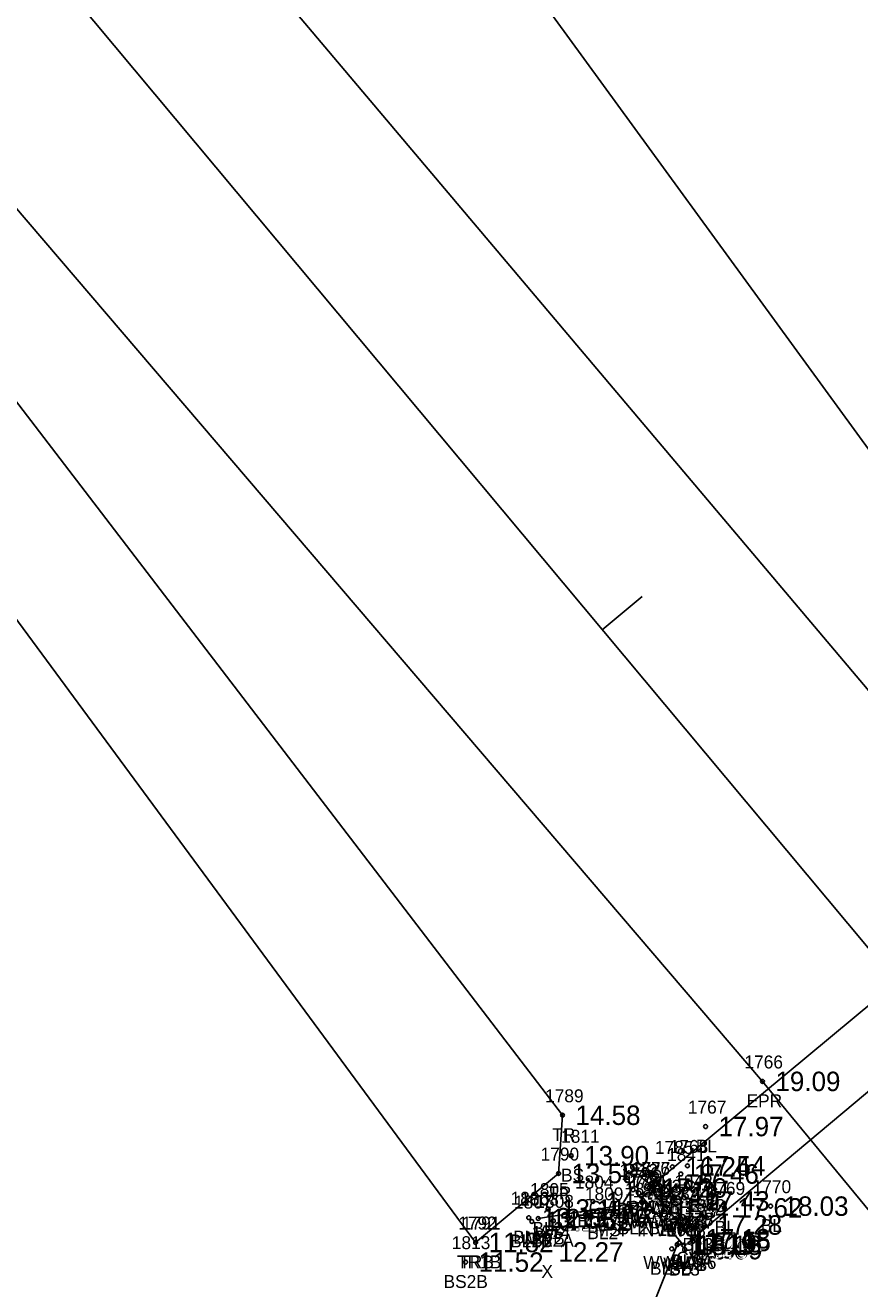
# Model space of a CAD drawing. Extents: x 2042117 to 2045853, y 303080 to 309569.
# Drawn here: x 2043937.2 to 2044001.6, y 305237.3 to 305334.8 of the extents above; entities that cross this region are included whole.
import ezdxf

# ---------------------------------------------------------------- set-up
doc = ezdxf.new("R2010")
doc.units = 0
for name, color, linetype in [('RD_DTM_BkLn_txCode', 7, 'Continuous'), ('RD_EX_Bridge', 7, 'Continuous'), ('RD_EX_Bridge_txCode', 7, 'Continuous'), ('RD_EX_Misc_txCode', 7, 'Continuous'), ('RD_EX_Road', 7, 'Continuous'), ('RD_EX_Road_txCode', 7, 'Continuous'), ('RD_EX_TX_Bridge_ELEV', 7, 'Continuous'), ('RD_EX_TX_Misc_ELEV', 7, 'Continuous'), ('RD_EX_TX_Road_ELEV', 7, 'Continuous'), ('RD_EX_TX_VEG_ELEV', 7, 'Continuous'), ('RD_EX_VEG', 7, 'Continuous'), ('RD_EX_VEG_txCode', 7, 'Continuous'), ('RD_HC_Cl', 7, 'Continuous'), ('RD_HC_Data_Tic', 7, 'Continuous'), ('RD_SMD_Locator', 7, 'Continuous')]:
    doc.layers.add(name, color=color, linetype=linetype)

msp = doc.modelspace()

# ---------------------------------------------------------------- linework, layer by layer
at = {"layer": 'RD_EX_Bridge'}
msp.add_line((2043984.777, 305244.422), (2043988.039, 305240.628), dxfattribs=at)
for points in [[(2043985.386, 305245.047), (2043988.72, 305241.13), (2044027.046, 305273.236), (2044023.87, 305277.035), (2043985.386, 305245.047)], [(2043984.895, 305244.066), (2043984.8, 305243.944), (2043976.82, 305242.688)], [(2043987.689, 305240.793), (2043987.547, 305240.669), (2043984.387, 305232.741)]]:
    msp.add_lwpolyline(points, dxfattribs=at)
at = {"layer": 'RD_EX_Road'}
for points in [[(2043522.114, 305819.999), (2043547.67, 305789.846), (2043610.716, 305713.317), (2043674.952, 305636.321), (2043738.181, 305559.625), (2043802.423, 305482.711), (2043865.72, 305405.842), (2043929.527, 305328.852), (2043994.128, 305253.275), (2044057.402, 305176.499), (2044121.268, 305100.203), (2044185.29, 305023.535), (2044249.556, 304947.279), (2044313.307, 304870.314), (2044377.087, 304793.291), (2044441.996, 304716.26), (2044505.918, 304639.554), (2044570.444, 304562.352), (2044634.611, 304485.931), (2044698.462, 304409.271), (2044762.461, 304332.365)], [(2043821.87, 305499.098), (2043885.809, 305423.073), (2043949.559, 305345.929), (2044013.411, 305270.34), (2044077.969, 305194.148), (2044141.399, 305117.67), (2044205.924, 305040.831), (2044269.544, 304964.65), (2044331.732, 304891.037), (2044335.217, 304889.195), (2044346.013, 304875.314), (2044356.182, 304867.608), (2044370.01, 304868.141), (2044386.833, 304866.361), (2044389.438, 304849.531), (2044390.713, 304830.729), (2044393.769, 304818.438), (2044395.505, 304814.177), (2044398.156, 304811.088)]]:
    msp.add_lwpolyline(points, dxfattribs=at)
at = {"layer": 'RD_EX_VEG'}
for points in [[(2043547.512, 305881.496), (2043539.704, 305861.319), (2043541.738, 305855.072), (2043567.734, 305828.704), (2043642.401, 305738.289), (2043706.881, 305661.84), (2043768.334, 305586.863), (2043834.286, 305506.383), (2043895.633, 305432.164), (2043964.517, 305353.987), (2044012.412, 305288.228), (2044020.961, 305286.081), (2044026.635, 305287.127), (2044039.882, 305282.355)], [(2043510.516, 305810.422), (2043502.87, 305810.614), (2043504.866, 305802.248), (2043509.115, 305791.368), (2043594.274, 305695.691), (2043658.161, 305620.889), (2043717.857, 305542.894), (2043784.348, 305466.308), (2043848.974, 305392.369), (2043916.007, 305316.786), (2043971.984, 305240.839)], [(2043510.516, 305810.422), (2043528.576, 305788.549), (2043603.52, 305706.798), (2043669.107, 305631.483), (2043746.08, 305529.273), (2043781.83, 305496.014), (2043793.112, 305482.335), (2043857.161, 305399.039), (2043922.607, 305323.928), (2043978.692, 305250.662), (2043978.387, 305246.162), (2043971.984, 305240.839)]]:
    msp.add_lwpolyline(points, dxfattribs=at)
at = {"layer": 'RD_HC_Cl'}
msp.add_line((2043284.298, 306123.239), (2045221.309, 303803.998), dxfattribs=at)
at = {"layer": 'RD_HC_Data_Tic'}
msp.add_line((2043981.766, 305288.14), (2043984.836, 305290.704), dxfattribs=at)
at = {"layer": 'RD_SMD_Locator'}
for centre in [(2043994.128, 305253.275), (2043978.692, 305250.662), (2043989.737, 305249.789), (2043979.36, 305247.538), (2043987.173, 305246.68), (2043988.335, 305246.753), (2043978.387, 305246.162), (2043987.826, 305246.125), (2043984.139, 305244.907), (2043984.596, 305244.651), (2043984.777, 305244.422), (2043985.386, 305245.047), (2043985.386, 305245.047), (2043977.578, 305243.425), (2043981.036, 305244.002), (2043984.624, 305243.458), (2043984.8, 305243.944), (2043984.895, 305244.066), (2043988.659, 305244.049), (2043991.187, 305243.513), (2043994.754, 305243.646), (2043976.087, 305242.751), (2043976.326, 305242.457), (2043976.82, 305242.688), (2043977.982, 305242.512), (2043981.806, 305243.093), (2043989.627, 305242.189), (2043971.984, 305240.839), (2043971.984, 305240.839), (2043987.547, 305240.669), (2043987.689, 305240.793), (2043988.039, 305240.628), (2043988.72, 305241.13), (2043988.758, 305240.917), (2043987.122, 305240.347), (2043988.119, 305240.286), (2043971.209, 305239.325)]:
    msp.add_circle(centre, 0.15, dxfattribs=at)

# ---------------------------------------------------------------- texts
at = {"layer": 'RD_DTM_BkLn_txCode'}
for s, p in [('1767', (2043988.367, 305250.789)), ('1811', (2043978.58, 305248.538)), ('1785', (2043985.826, 305247.68)), ('1768', (2043986.965, 305247.753)), ('BL', (2043988.981, 305247.789)), ('1841', (2043986.763, 305247.125)), ('BS', (2043978.58, 305245.538)), ('1812', (2043983.076, 305245.907)), ('1786', (2043983.226, 305245.651)), ('1804', (2043979.65, 305245.002)), ('BL2A', (2043985.48, 305244.68)), ('1842', (2043987.313, 305245.049)), ('BL', (2043987.579, 305244.753)), ('1769', (2043989.817, 305244.513)), ('1770', (2043993.368, 305244.646)), ('1806', (2043974.678, 305243.751)), ('1805', (2043976.192, 305244.425)), ('1809', (2043980.42, 305244.093)), ('1810', (2043983.522, 305244.458)), ('BL3A', (2043986.133, 305244.125)), ('1807', (2043974.94, 305243.457)), ('1808', (2043976.596, 305243.512)), ('BSB', (2043982.887, 305242.907)), ('BL2', (2043983.391, 305242.651)), ('1843', (2043988.28, 305243.189)), ('BL2', (2043979.831, 305242.002)), ('1787', (2043987.411, 305241.917)), ('BL3', (2043987.455, 305242.049)), ('BL', (2043993.998, 305241.646)), ('BL2', (2043974.882, 305240.751)), ('BL2', (2043976.373, 305241.425)), ('BL2', (2043980.601, 305241.093)), ('BL2B', (2043982.947, 305241.458)), ('1801', (2043986.019, 305241.347)), ('1788', (2043986.773, 305241.286)), ('BL', (2043990.431, 305241.513)), ('1813', (2043970.146, 305240.325)), ('BL2B', (2043974.649, 305240.457)), ('BL2A', (2043976.289, 305240.512)), ('BL3B', (2043987.95, 305240.189)), ('BL3A', (2043987.065, 305238.917)), ('BL3B', (2043985.444, 305238.347)), ('BL3', (2043986.915, 305238.286)), ('BS2B', (2043969.508, 305237.325))]:
    msp.add_text(s, height=1, dxfattribs=at).set_placement(p)
at = {"layer": 'RD_EX_Bridge_txCode'}
for s, p in [('1826', (2043984.016, 305246.047)), ('1777', (2043984.039, 305246.047)), ('1779', (2043983.431, 305245.422)), ('1782', (2043983.454, 305244.944)), ('1781', (2043983.832, 305245.066)), ('1803', (2043975.434, 305243.688)), ('CVLA 4W 6H', (2043980.724, 305243.047)), ('CVLB', (2043983.669, 305243.047)), ('WWA .6', (2043982.297, 305242.066)), ('HWA .9', (2043982.289, 305242.422)), ('WW', (2043983.895, 305241.944)), ('1784', (2043986.201, 305241.669)), ('1783', (2043986.342, 305241.793)), ('1780', (2043986.653, 305241.628)), ('1778', (2043987.374, 305242.13)), ('WWB', (2043975.442, 305240.688)), ('WW1A .6', (2043984.925, 305238.793)), ('WW1', (2043986.477, 305238.669)), ('CVL', (2043987.476, 305239.13)), ('HWB', (2043986.747, 305238.628))]:
    msp.add_text(s, height=1, dxfattribs=at).set_placement(p)
at = {"layer": 'RD_EX_Misc_txCode'}
for s, p in [('1802', (2043984.118, 305244.326)), ('1814', (2043976.317, 305241.11)), ('MSP INVERT', (2043981.181, 305241.326)), ('X', (2043977.065, 305238.11))]:
    msp.add_text(s, height=1, dxfattribs=at).set_placement(p)
at = {"layer": 'RD_EX_Road_txCode'}
for s, p in [('1766', (2043992.734, 305254.275)), ('EPR', (2043992.899, 305251.275))]:
    msp.add_text(s, height=1, dxfattribs=at).set_placement(p)
at = {"layer": 'RD_EX_TX_Bridge_ELEV'}
for s, p in [('17.20', (2043986.386, 305244.297)), ('17.20', (2043986.386, 305244.297)), ('18.16', (2043985.777, 305243.672)), ('17.20', (2043985.8, 305243.194)), ('17.17', (2043985.895, 305243.316)), ('12.58', (2043977.82, 305241.938)), ('17.18', (2043989.72, 305240.38)), ('17.19', (2043988.547, 305239.919)), ('17.19', (2043988.689, 305240.043)), ('18.18', (2043989.039, 305239.878))]:
    msp.add_text(s, height=1.5, dxfattribs=at).set_placement(p)
at = {"layer": 'RD_EX_TX_Misc_ELEV'}
for s, p in [('17.97', (2043990.737, 305249.039)), ('13.90', (2043980.36, 305246.788)), ('17.54', (2043989.335, 305246.003)), ('16.24', (2043988.173, 305245.93)), ('17.46', (2043988.826, 305245.375)), ('14.33', (2043985.139, 305244.157)), ('14.24', (2043982.036, 305243.252)), ('14.23', (2043985.596, 305243.901)), ('17.43', (2043989.659, 305243.299)), ('13.11', (2043978.578, 305242.675)), ('11.49', (2043982.806, 305242.343)), ('11.36', (2043985.624, 305242.708)), ('10.64', (2043986.504, 305242.576)), ('17.62', (2043992.187, 305242.763)), ('18.03', (2043995.754, 305242.896)), ('13.13', (2043977.087, 305242.001)), ('13.15', (2043977.326, 305241.707)), ('12.62', (2043978.982, 305241.762)), ('17.28', (2043990.627, 305241.439)), ('16.55', (2043989.758, 305240.167)), ('12.27', (2043978.38, 305239.36)), ('11.39', (2043988.122, 305239.597)), ('16.09', (2043989.119, 305239.536)), ('11.52', (2043972.209, 305238.575))]:
    msp.add_text(s, height=1.5, dxfattribs=at).set_placement(p)
at = {"layer": 'RD_EX_TX_Road_ELEV'}
msp.add_text('19.09', height=1.5, dxfattribs=at).set_placement((2043995.128, 305252.525))
at = {"layer": 'RD_EX_TX_VEG_ELEV'}
for s, p in [('14.58', (2043979.692, 305249.912)), ('13.58', (2043979.387, 305245.412)), ('11.82', (2043972.984, 305240.089)), ('11.82', (2043972.984, 305240.089))]:
    msp.add_text(s, height=1.5, dxfattribs=at).set_placement(p)
at = {"layer": 'RD_EX_VEG_txCode'}
for s, p in [('1789', (2043977.345, 305251.662)), ('TR', (2043977.896, 305248.662)), ('1790', (2043977.001, 305247.162)), ('TR', (2043977.592, 305244.162)), ('1792', (2043970.638, 305241.839)), ('1791', (2043970.921, 305241.839)), ('TR1B', (2043970.551, 305238.839)), ('TRB', (2043970.717, 305238.839))]:
    msp.add_text(s, height=1, dxfattribs=at).set_placement(p)

doc.saveas('drawing.dxf')
